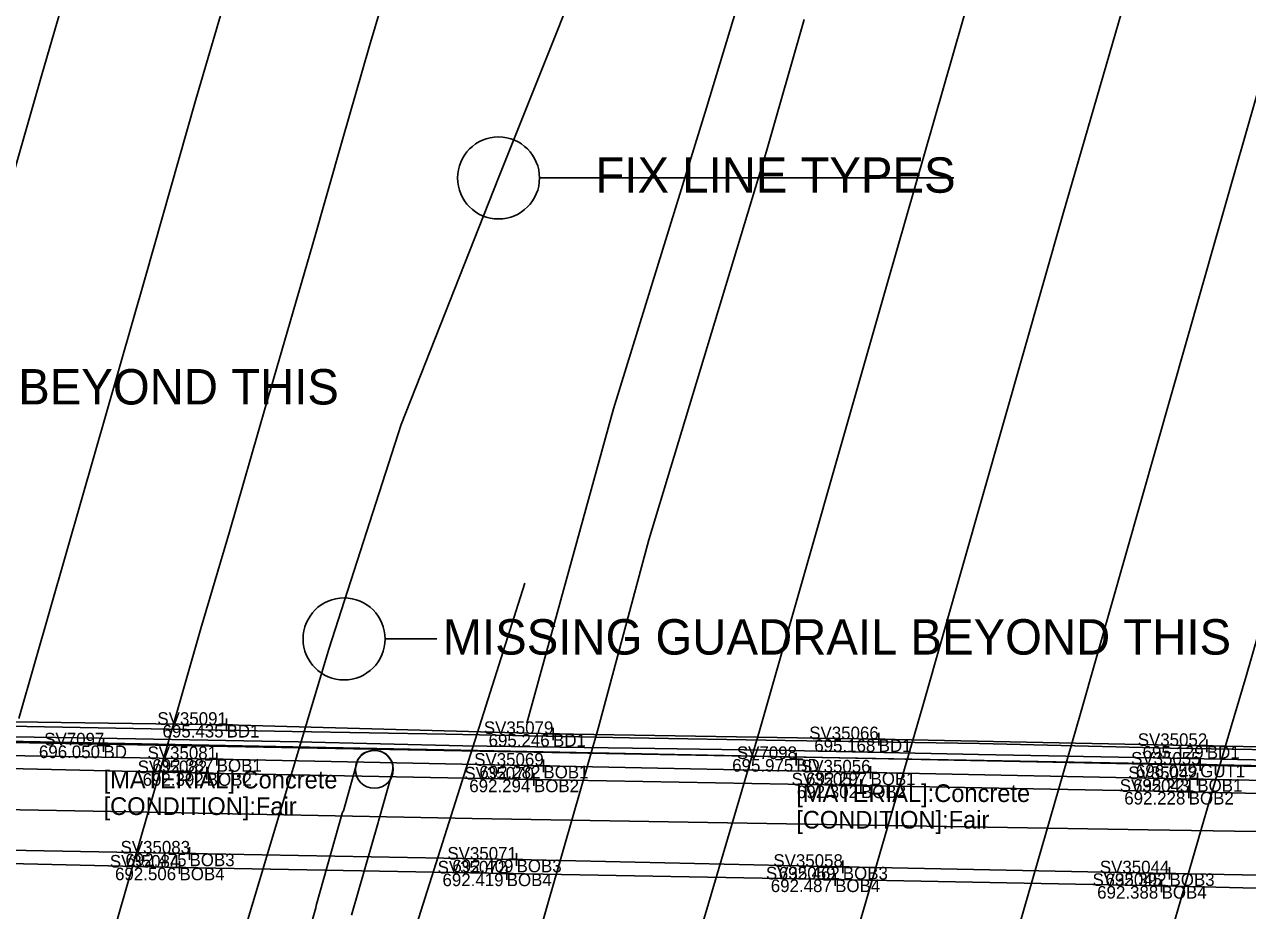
# Model space of a CAD drawing. Extents: x 1659932 to 1663108, y 619867 to 620611.
# Drawn here: x 1661352.9 to 1661449.7, y 620235.1 to 620305.2 of the extents above; entities that cross this region are included whole.
import ezdxf

# ---------------------------------------------------------------- set-up
doc = ezdxf.new("R2010")
doc.units = 0
for name, color, linetype in [('BR_X_Rail_Object', 7, 'Continuous'), ('BR_X_SV_Bottom_of_Beam', 7, 'Continuous'), ('BR_X_SV_Bottom_of_Beam_Text', 7, 'Continuous'), ('BR_X_SV_Deck_Top', 7, 'Continuous'), ('BR_X_SV_Deck_Top_Text', 7, 'Continuous'), ('BR_X_SV_Pier_Cap_Top', 7, 'Continuous'), ('PM_X_Edge_Line', 7, 'Continuous'), ('PM_X_Lane_Line', 7, 'Continuous'), ('PV_X_Curb', 7, 'Continuous'), ('PV_X_EOP', 7, 'Continuous'), ('RD_X_Fence', 7, 'Continuous'), ('RD_X_GR_Lt', 7, 'Continuous'), ('SC_Scratch6', 7, 'Continuous'), ('SV_X_Break_Lines', 7, 'Continuous'), ('SV_X_Shot_Marker', 7, 'Continuous'), ('SV_X_Text', 7, 'Continuous'), ('SV_X_Text_Comment', 7, 'Continuous'), ('SV_X_Text_Elevation', 7, 'Continuous'), ('SV_X_Text_Name', 7, 'Continuous')]:
    doc.layers.add(name, color=color, linetype=linetype)

msp = doc.modelspace()

# ---------------------------------------------------------------- linework, layer by layer
at = {"layer": 'BR_X_Rail_Object'}
for points in [[(1661456.593, 620247.691), (1661443.635, 620247.905), (1661428.534, 620248.273), (1661413.142, 620248.511), (1661400.818, 620248.725), (1661386.306, 620248.998), (1661374.126, 620249.215), (1661358.768, 620249.507), (1661343.2, 620249.805), (1661327.988, 620250.095), (1661312.412, 620250.402), (1661292.245, 620250.78)], [(1661292.272, 620249.911), (1661312.353, 620249.471), (1661327.657, 620249.198), (1661343.357, 620248.923), (1661358.834, 620248.687), (1661374.599, 620248.399), (1661387.622, 620248.077), (1661401.062, 620247.89), (1661413.423, 620247.709), (1661428.457, 620247.387), (1661443.687, 620247.108), (1661456.879, 620246.848)]]:
    msp.add_lwpolyline(points, dxfattribs=at)
at = {"layer": 'BR_X_SV_Bottom_of_Beam'}
for points in [[(1661523.404, 620243.849), (1661497.415, 620244.383), (1661471.694, 620244.95), (1661445.773, 620245.45), (1661419.903, 620245.974), (1661394.009, 620246.51), (1661368.147, 620247.032), (1661342.287, 620247.488), (1661316.311, 620248.045), (1661290.557, 620248.602), (1661264.648, 620249.031), (1661238.6, 620249.579)], [(1661517.582, 620243.008), (1661496.897, 620243.44), (1661470.919, 620243.838), (1661445.09, 620244.441), (1661419.147, 620244.946), (1661393.26, 620245.417), (1661367.358, 620245.921), (1661341.629, 620246.518), (1661315.646, 620247.115), (1661289.746, 620247.518), (1661264.383, 620248.322), (1661238.204, 620248.614)], [(1661521.265, 620236.365), (1661495.332, 620236.959), (1661469.491, 620237.512), (1661443.572, 620237.996), (1661417.708, 620238.508), (1661391.884, 620239.08), (1661365.994, 620239.561), (1661340.119, 620240.034), (1661314.197, 620240.589), (1661288.354, 620241.145), (1661262.476, 620241.611), (1661236.623, 620242.15)], [(1661520.605, 620235.452), (1661494.63, 620235.975), (1661468.71, 620236.383), (1661442.944, 620236.996), (1661417.103, 620237.514), (1661391.103, 620237.982), (1661365.202, 620238.448), (1661339.374, 620239.07), (1661313.502, 620239.591), (1661287.59, 620239.99), (1661261.723, 620240.632), (1661235.908, 620241.144)]]:
    msp.add_lwpolyline(points, dxfattribs=at)
at = {"layer": 'BR_X_SV_Deck_Top'}
msp.add_lwpolyline([(1661524.154, 620246.519), (1661498.291, 620247.067), (1661472.426, 620247.598), (1661446.524, 620248.074), (1661420.55, 620248.604), (1661394.772, 620249.021), (1661368.927, 620249.743), (1661342.743, 620250.117), (1661316.866, 620250.706), (1661291.246, 620251.013), (1661265.132, 620251.796)], dxfattribs=at)
at = {"layer": 'BR_X_SV_Pier_Cap_Top'}
for points in [[(1661373.92, 620228.026), (1661375.992, 620235.256), (1661376.016, 620235.45), (1661378.105, 620242.845), (1661378.176, 620242.951), (1661379.324, 620247.001), (1661379.63, 620247.4), (1661379.809, 620247.522), (1661380.162, 620247.643), (1661380.667, 620247.738), (1661381.121, 620247.661), (1661381.539, 620247.452), (1661381.799, 620247.133), (1661382.008, 620246.835), (1661382.075, 620246.593), (1661382.095, 620246.287), (1661382.038, 620245.951)], [(1661382.038, 620245.951), (1661380.96, 620242.113), (1661380.938, 620242.011), (1661378.818, 620234.677)]]:
    msp.add_lwpolyline(points, dxfattribs=at)
at = {"layer": 'PM_X_Edge_Line'}
for p, q in [((1661400.11, 620212.126), (1661411.11, 620249.281)), ((1661448.095, 620248.463), (1661437.387, 620211.448))]:
    msp.add_line(p, q, dxfattribs=at)
for points in [[(1661447.145, 620578.178), (1661442.077, 620560.708), (1661436.663, 620541.934), (1661430.963, 620522.042), (1661424.5, 620499.705), (1661417.8, 620476.462), (1661410.387, 620450.904), (1661399.15, 620411.876), (1661394.241, 620394.792), (1661380.03, 620345.601), (1661374.374, 620326.103), (1661366.485, 620299.21), (1661362.47, 620285.108), (1661357.431, 620267.557), (1661352.489, 620250.244)], [(1661533.637, 620545.425), (1661528.108, 620526.358), (1661523.208, 620509.615), (1661518.012, 620491.429), (1661511.994, 620470.167), (1661507.322, 620453.725), (1661502.995, 620438.636), (1661498.703, 620424.135), (1661495.255, 620412.323), (1661490.204, 620394.571), (1661483.245, 620370.315), (1661475.775, 620344.717), (1661468.35, 620318.812), (1661463.705, 620302.949), (1661458.897, 620285.652), (1661453.934, 620268.511), (1661449.632, 620253.601), (1661448.095, 620248.463)], [(1661411.11, 620249.281), (1661421.228, 620284.646), (1661427.959, 620308.09), (1661435.85, 620335.403), (1661443.675, 620362.669)], [(1661550.118, 620239.201), (1661538.667, 620239.519), (1661512.091, 620240.179), (1661488.878, 620240.663), (1661465.84, 620241.071), (1661441.891, 620241.445), (1661414.819, 620241.887), (1661388.375, 620242.338), (1661361.281, 620242.854), (1661333.713, 620243.371), (1661302.167, 620244.004), (1661273.353, 620244.591), (1661246.421, 620245.132), (1661216.402, 620245.664), (1661208.501, 620245.807)]]:
    msp.add_lwpolyline(points, dxfattribs=at)
at = {"layer": 'PM_X_Lane_Line'}
for p, q in [((1661409.184, 620200.168), (1661424.053, 620251.255)), ((1661436.528, 620250.631), (1661421.891, 620200.155))]:
    msp.add_line(p, q, dxfattribs=at)
for points in [[(1661431.963, 620570.296), (1661421.037, 620532.095), (1661410.698, 620495.596), (1661399.418, 620457.063), (1661388.158, 620417.769), (1661377.14, 620379.938), (1661365.696, 620340.362), (1661354.268, 620301.081), (1661343.5, 620263.546)], [(1661424.053, 620251.255), (1661435.153, 620290.2), (1661446.11, 620327.936), (1661457.551, 620367.377), (1661469.01, 620406.958), (1661480.912, 620448.46), (1661491.719, 620486.444), (1661502.566, 620523.803), (1661513.733, 620562.475)], [(1661525.681, 620560.345), (1661514.724, 620522.512), (1661503.087, 620483.055), (1661491.598, 620443.157), (1661480.26, 620403.462), (1661469.087, 620364.672), (1661458.332, 620327.003), (1661447.315, 620288.523), (1661436.528, 620250.631)]]:
    msp.add_lwpolyline(points, dxfattribs=at)
at = {"layer": 'PV_X_Curb'}
msp.add_lwpolyline([(1661523.342, 620245.121), (1661471.566, 620246.113), (1661445.996, 620246.597), (1661316.22, 620249.01), (1661290.79, 620249.439), (1661264.952, 620250.247), (1661238.714, 620250.79)], dxfattribs=at)
at = {"layer": 'PV_X_EOP'}
for p, q in [((1661364.882, 620250.347), (1661354.068, 620212.758)), ((1661387.682, 620212.413), (1661398.34, 620249.454))]:
    msp.add_line(p, q, dxfattribs=at)
for points in [[(1661382.863, 620312.254), (1661380.233, 620303.47), (1661378.07, 620295.951), (1661375.745, 620287.797), (1661371.987, 620274.83), (1661369.154, 620265.019), (1661366.896, 620257.366), (1661364.882, 620250.347)], [(1661414.66, 620305.548), (1661411.665, 620295.133), (1661402.355, 620264.395), (1661398.34, 620249.454)]]:
    msp.add_lwpolyline(points, dxfattribs=at)
at = {"layer": 'RD_X_Fence'}
msp.add_lwpolyline([(1661392.698, 620249.89), (1661399.552, 620274.746), (1661406.928, 620298.575), (1661411.128, 620312.514), (1661421.743, 620349.208), (1661428.857, 620374.884), (1661434.079, 620399.318), (1661445.827, 620441.195)], dxfattribs=at)
at = {"layer": 'RD_X_GR_Lt'}
for p, q in [((1661376.955, 620211.812), (1661392.542, 620260.947)), ((1661377.013, 620255.729), (1661361.042, 620202.435))]:
    msp.add_line(p, q, dxfattribs=at)
msp.add_lwpolyline([(1661415.499, 620366.847), (1661402.134, 620322.676), (1661395.195, 620304.892), (1661390.454, 620293.012), (1661382.736, 620273.505), (1661377.013, 620255.729)], dxfattribs=at)
at = {"layer": 'SC_Scratch6'}
for p, q in [((1661393.698, 620293.012), (1661426.502, 620293.012)), ((1661381.472, 620256.539), (1661385.562, 620256.539))]:
    msp.add_line(p, q, dxfattribs=at)
for centre in [(1661390.454, 620293.012), (1661378.227, 620256.539)]:
    msp.add_circle(centre, 3.245, dxfattribs=at)
at = {"layer": 'SV_X_Break_Lines'}
msp.add_lwpolyline([(1661238.016, 620250.735), (1661242.286, 620250.672), (1661247.517, 620250.551), (1661257.182, 620250.394), (1661265.859, 620250.202), (1661279.254, 620249.879), (1661300.715, 620249.466), (1661326.88, 620248.933), (1661355.543, 620248.374), (1661388.796, 620247.704), (1661434.33, 620246.78), (1661467.071, 620246.096), (1661484, 620245.717), (1661498.395, 620245.527), (1661509.52, 620245.356), (1661518.819, 620245.069), (1661524.432, 620245.01)], dxfattribs=at)
msp.add_circle((1661380.622, 620246.225), 1.5, dxfattribs=at)
at = {"layer": 'SV_X_Shot_Marker'}
for p, q in [((1661368.427, 620249.743), (1661369.427, 620249.743)), ((1661368.927, 620250.243), (1661368.927, 620249.243)), ((1661368.927, 620249.743), (1661368.927, 620249.743)), ((1661394.272, 620249.021), (1661395.272, 620249.021)), ((1661394.772, 620249.521), (1661394.772, 620248.521)), ((1661394.772, 620249.021), (1661394.772, 620249.021)), ((1661420.55, 620249.104), (1661420.55, 620248.104)), ((1661358.686, 620248.113), (1661359.686, 620248.113)), ((1661359.186, 620248.613), (1661359.186, 620247.613)), ((1661359.186, 620248.113), (1661359.186, 620248.113)), ((1661420.05, 620248.604), (1661421.05, 620248.604)), ((1661420.55, 620248.604), (1661420.55, 620248.604)), ((1661446.024, 620248.074), (1661447.024, 620248.074)), ((1661446.524, 620248.574), (1661446.524, 620247.574)), ((1661446.524, 620248.074), (1661446.524, 620248.074)), ((1661367.647, 620247.032), (1661368.647, 620247.032)), ((1661368.147, 620247.532), (1661368.147, 620246.532)), ((1661368.147, 620247.032), (1661368.147, 620247.032)), ((1661394.009, 620247.01), (1661394.009, 620246.01)), ((1661413.521, 620247.039), (1661414.521, 620247.039)), ((1661414.021, 620247.539), (1661414.021, 620246.539)), ((1661414.021, 620247.039), (1661414.021, 620247.039)), ((1661445.996, 620247.097), (1661445.996, 620246.097)), ((1661366.858, 620245.921), (1661367.858, 620245.921)), ((1661367.358, 620246.421), (1661367.358, 620245.421)), ((1661367.358, 620245.921), (1661367.358, 620245.921)), ((1661393.26, 620245.917), (1661393.26, 620244.917)), ((1661393.509, 620246.51), (1661394.509, 620246.51)), ((1661394.009, 620246.51), (1661394.009, 620246.51)), ((1661419.403, 620245.974), (1661420.403, 620245.974)), ((1661419.903, 620246.474), (1661419.903, 620245.474)), ((1661419.903, 620245.974), (1661419.903, 620245.974)), ((1661445.496, 620246.597), (1661446.496, 620246.597)), ((1661445.773, 620245.95), (1661445.773, 620244.95)), ((1661445.996, 620246.597), (1661445.996, 620246.597)), ((1661392.76, 620245.417), (1661393.76, 620245.417)), ((1661393.26, 620245.417), (1661393.26, 620245.417)), ((1661418.647, 620244.946), (1661419.647, 620244.946)), ((1661419.147, 620245.446), (1661419.147, 620244.446)), ((1661419.147, 620244.946), (1661419.147, 620244.946)), ((1661445.09, 620244.941), (1661445.09, 620243.941)), ((1661445.273, 620245.45), (1661446.273, 620245.45)), ((1661445.773, 620245.45), (1661445.773, 620245.45)), ((1661444.59, 620244.441), (1661445.59, 620244.441)), ((1661445.09, 620244.441), (1661445.09, 620244.441)), ((1661365.994, 620240.061), (1661365.994, 620239.061)), ((1661365.202, 620238.948), (1661365.202, 620237.948)), ((1661365.494, 620239.561), (1661366.494, 620239.561)), ((1661365.994, 620239.561), (1661365.994, 620239.561)), ((1661391.384, 620239.08), (1661392.384, 620239.08)), ((1661391.884, 620239.58), (1661391.884, 620238.58)), ((1661391.884, 620239.08), (1661391.884, 620239.08)), ((1661417.708, 620239.008), (1661417.708, 620238.008)), ((1661364.702, 620238.448), (1661365.702, 620238.448)), ((1661365.202, 620238.448), (1661365.202, 620238.448)), ((1661390.603, 620237.982), (1661391.603, 620237.982)), ((1661391.103, 620238.482), (1661391.103, 620237.482)), ((1661391.103, 620237.982), (1661391.103, 620237.982)), ((1661417.103, 620238.014), (1661417.103, 620237.014)), ((1661417.208, 620238.508), (1661418.208, 620238.508)), ((1661417.708, 620238.508), (1661417.708, 620238.508)), ((1661443.072, 620237.996), (1661444.072, 620237.996)), ((1661443.572, 620238.496), (1661443.572, 620237.496)), ((1661443.572, 620237.996), (1661443.572, 620237.996)), ((1661416.603, 620237.514), (1661417.603, 620237.514)), ((1661417.103, 620237.514), (1661417.103, 620237.514)), ((1661442.944, 620237.496), (1661442.944, 620236.496)), ((1661442.444, 620236.996), (1661443.444, 620236.996)), ((1661442.944, 620236.996), (1661442.944, 620236.996))]:
    msp.add_line(p, q, dxfattribs=at)

# ---------------------------------------------------------------- texts
at = {"layer": 'BR_X_SV_Bottom_of_Beam_Text'}
for s, p in [('SV35081', (1661362.669, 620247.032)), ('SV35082', (1661361.889, 620245.921)), ('692.387', (1661363.051, 620246.032)), ('BOB1', (1661368.147, 620246.032)), ('SV35069', (1661388.529, 620246.51)), ('SV35056', (1661414.403, 620245.974)), ('692.392', (1661362.285, 620244.921)), ('BOB2', (1661367.358, 620244.921)), ('SV35070', (1661387.75, 620245.417)), ('692.282', (1661388.936, 620245.51)), ('BOB1', (1661394.009, 620245.51)), ('SV35057', (1661413.655, 620244.946)), ('692.297', (1661414.807, 620244.974)), ('BOB1', (1661419.903, 620244.974)), ('SV35042', (1661440.304, 620245.45)), ('692.294', (1661388.138, 620244.417)), ('BOB2', (1661393.26, 620244.417)), ('692.302', (1661414.074, 620243.946)), ('BOB2', (1661419.147, 620243.946)), ('SV35043', (1661439.63, 620244.441)), ('692.221', (1661440.691, 620244.45)), ('BOB1', (1661445.773, 620244.45)), ('692.228', (1661439.99, 620243.441)), ('BOB2', (1661445.09, 620243.441)), ('SV35083', (1661360.534, 620239.561)), ('SV35071', (1661386.406, 620239.08)), ('SV35084', (1661359.684, 620238.448)), ('692.475', (1661360.924, 620238.561)), ('BOB3', (1661365.994, 620238.561)), ('SV35072', (1661385.634, 620237.982)), ('692.409', (1661386.8, 620238.08)), ('BOB3', (1661391.884, 620238.08)), ('SV35058', (1661412.211, 620238.508)), ('SV35044', (1661438.054, 620237.996)), ('692.506', (1661360.098, 620237.448)), ('BOB4', (1661365.202, 620237.448)), ('692.419', (1661386.019, 620236.982)), ('BOB4', (1661391.103, 620236.982)), ('SV35059', (1661411.623, 620237.514)), ('692.462', (1661412.635, 620237.508)), ('BOB3', (1661417.708, 620237.508)), ('SV35045', (1661437.477, 620236.996)), ('692.392', (1661438.499, 620236.996)), ('BOB3', (1661443.572, 620236.996)), ('692.487', (1661412.007, 620236.514)), ('BOB4', (1661417.103, 620236.514)), ('692.388', (1661437.844, 620235.996)), ('BOB4', (1661442.944, 620235.996))]:
    msp.add_text(s, height=1, dxfattribs=at).set_placement(p)
at = {"layer": 'BR_X_SV_Deck_Top_Text'}
for s, p in [('SV35091', (1661363.449, 620249.743)), ('695.435', (1661363.857, 620248.743)), ('BD1', (1661368.927, 620248.743)), ('SV35079', (1661389.292, 620249.021)), ('SV35066', (1661415.05, 620248.604)), ('SV7097', (1661354.492, 620248.113)), ('695.246', (1661389.668, 620248.021)), ('BD1', (1661394.772, 620248.021)), ('SV35052', (1661441.055, 620248.074)), ('696.050', (1661354.072, 620247.113)), ('BD', (1661359.186, 620247.113)), ('SV7098', (1661409.322, 620247.039)), ('695.168', (1661415.45, 620247.604)), ('BD1', (1661420.55, 620247.604)), ('695.129', (1661441.44, 620247.074)), ('BD1', (1661446.524, 620247.074)), ('695.975', (1661408.951, 620246.039)), ('BD', (1661414.021, 620246.039))]:
    msp.add_text(s, height=1, dxfattribs=at).set_placement(p)
at = {"layer": 'SC_Scratch6'}
for s, p in [('FIX LINE TYPES', (1661398.128, 620291.845)), ('MISSING GUADRAIL BEYOND THIS', (1661315.401, 620275.092)), ('MISSING GUADRAIL BEYOND THIS', (1661386.031, 620255.303))]:
    msp.add_text(s, height=2.79999, dxfattribs=at).set_placement(p)
at = {"layer": 'SV_X_Text'}
for s, p in [('[MATERIAL]:Concrete', (1661359.186, 620244.713)), ('[MATERIAL]:Concrete', (1661414.021, 620243.639)), ('[CONDITION]:Fair', (1661359.186, 620242.613)), ('[CONDITION]:Fair', (1661414.021, 620241.539))]:
    msp.add_text(s, height=1.4, dxfattribs=at).set_placement(p)
at = {"layer": 'SV_X_Text_Comment'}
msp.add_text('GUT1', height=1, dxfattribs=at).set_placement((1661445.996, 620245.597))
at = {"layer": 'SV_X_Text_Elevation'}
msp.add_text('696.059', height=1, dxfattribs=at).set_placement((1661440.912, 620245.597))
at = {"layer": 'SV_X_Text_Name'}
msp.add_text('SV35055', height=1, dxfattribs=at).set_placement((1661440.529, 620246.597))

doc.saveas('drawing.dxf')
